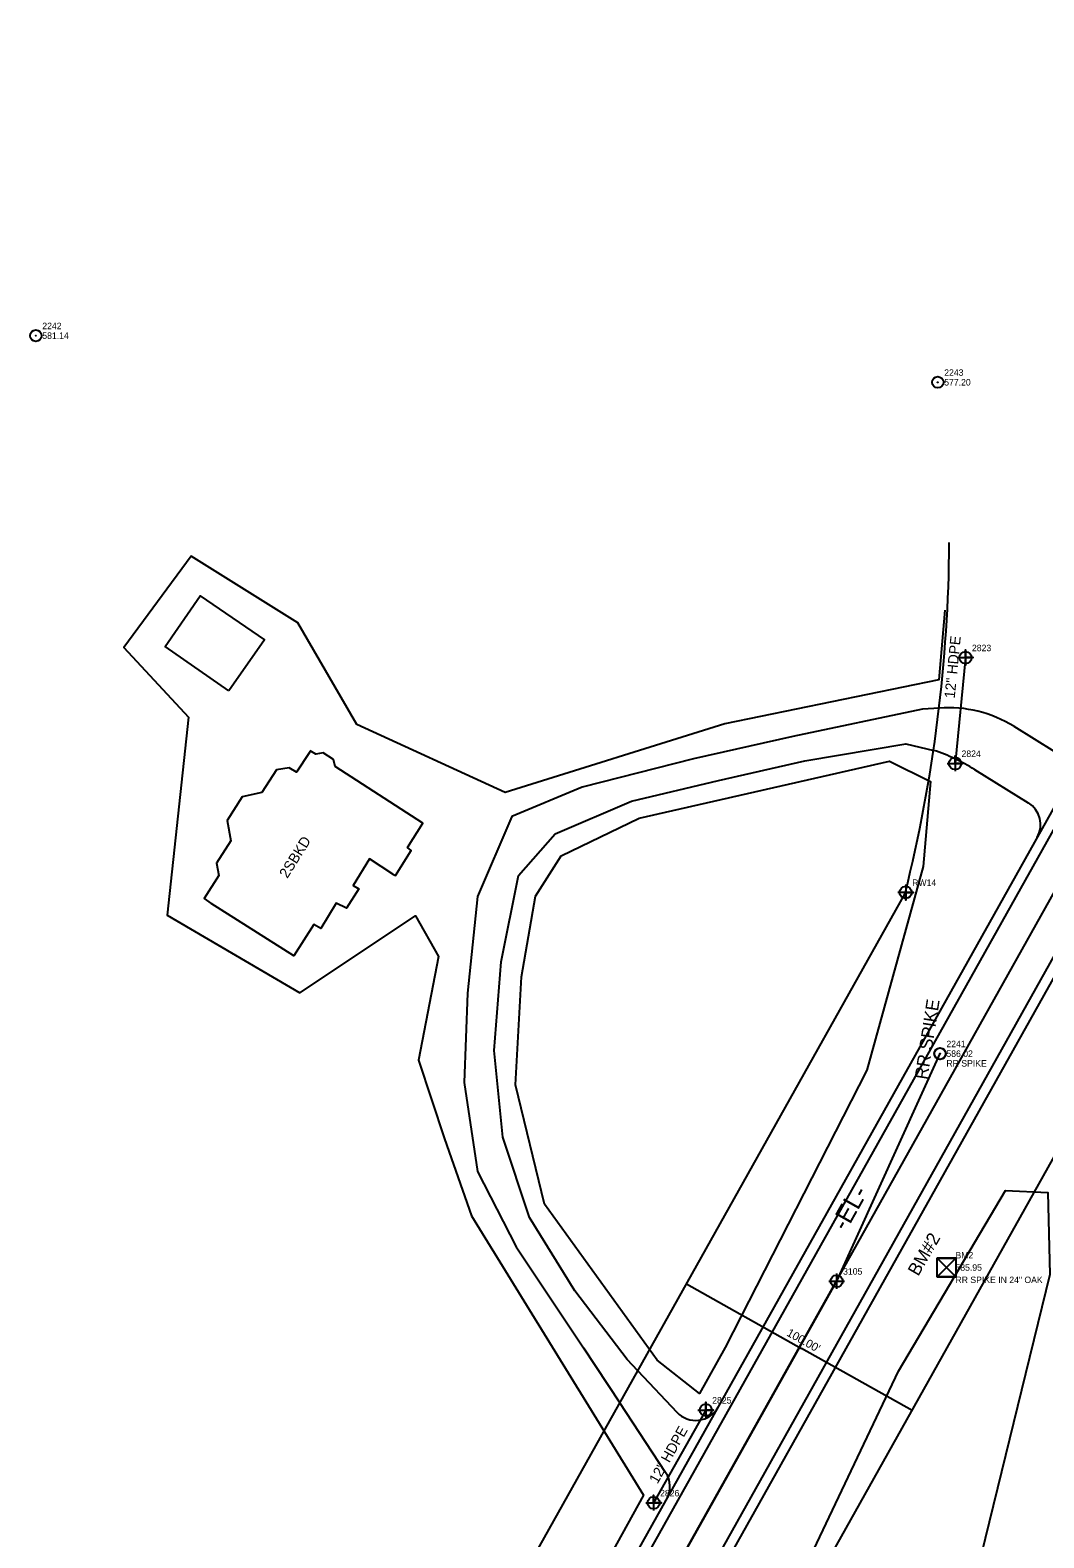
# Model space of a CAD drawing. Extents: x 1653123 to 1656194, y 596584 to 600233.
# Drawn here: x 1654087 to 1654478, y 599047 to 599629 of the extents above; entities that cross this region are included whole.
import ezdxf

# ---------------------------------------------------------------- set-up
doc = ezdxf.new("R2010")
doc.units = 0
for name, color, linetype in [('CTL Bench Mark CELL', 7, 'Continuous'), ('CTL Bench Mark Cogo Comment', 7, 'Continuous'), ('CTL Bench Mark Cogo Elevation', 7, 'Continuous'), ('CTL Bench Mark Cogo Number', 7, 'Continuous'), ('CTL Bench Mark Text', 7, 'Continuous'), ('Default Symbol CELL', 7, 'Continuous'), ('Default Symbol Cogo Number', 7, 'Continuous'), ('Exist Building Foundations', 7, 'Continuous'), ('Exist Building Text', 7, 'Continuous'), ('Exist Horizontal Alignment', 7, 'Continuous'), ('Exist Horizontal Alignment Direction Label', 7, 'Continuous'), ('Exist Property Iron Pin CELL', 7, 'Continuous'), ('Exist Property Iron Pin Cogo Comment', 7, 'Continuous'), ('Exist Property Iron Pin Cogo Elevation', 7, 'Continuous'), ('Exist Property Iron Pin Cogo Number', 7, 'Continuous'), ('Exist Property Iron Pin Text', 7, 'Continuous'), ('Exist Right of Way Line', 7, 'Continuous'), ('Exist Right of Way Width CELL', 7, 'Continuous'), ('Exist Roads EOT', 7, 'Continuous'), ('Exist Structure Minor Pipes HDPE 12 Inch', 7, 'Continuous'), ('Exist Structure Minor Pipes HDPE 12 Inch Cogo Number', 7, 'Continuous'), ('Exist Structure Minor Pipes HDPE 12 Inch Cogo Point CELL', 7, 'Continuous'), ('Exist Structure Minor Pipes HDPE 12 Inch Text', 7, 'Continuous'), ('Exist Vegetation Woods Line', 7, 'Continuous'), ('Prop Conc Shoulder Berm Gutter', 7, 'Continuous'), ('Prop Easement Construction', 7, 'Continuous'), ('Prop Easement Permanent Drainage Station Offsets', 7, 'Continuous'), ('Scratch_Level_5', 7, 'Continuous')]:
    doc.layers.add(name, color=color, linetype=linetype)

# ---------------------------------------------------------------- blocks, each defined once
blk = doc.blocks.new('EXIST STRUCTURE MINOR PIPES HDPE COGO POINT')
at = {"layer": 'Exist Structure Minor Pipes HDPE 12 Inch Cogo Point CELL'}
blk.add_lwpolyline([(-0.06, 0), (0.06, 0), (0, 0), (0, 0.06), (0, -0.06)], dxfattribs=at)
blk.add_circle((0, 0), 0.0469, dxfattribs=at)
blk = doc.blocks.new('EXIST PROPERTY IRON PIN')
at = {"layer": 'Exist Property Iron Pin CELL'}
for radius in [0.0441, 0.00141]:
    blk.add_circle((0.0015, 0), radius, dxfattribs=at)
blk = doc.blocks.new('DEFAULT SYMBOL')
at = {"layer": 'Default Symbol CELL'}
for points in [[(-0.06, 0), (0, 0)], [(0, 0.06), (0, 0)], [(0, 0), (0.06, 0)], [(0, 0), (0, -0.06)]]:
    blk.add_lwpolyline(points, dxfattribs=at)
blk.add_circle((0, 0), 0.0469, dxfattribs=at)

msp = doc.modelspace()

# ---------------------------------------------------------------- linework, layer by layer
at = {"layer": 'CTL Bench Mark CELL'}
msp.add_line((1654440.7, 599151.65), (1654440.7, 599151.65), dxfattribs=at)
msp.add_lwpolyline([(1654437.1, 599155.24), (1654444.29, 599155.24), (1654444.29, 599148.05), (1654437.1, 599148.05)], close=True, dxfattribs=at)
for points in [[(1654444.29, 599155.24), (1654437.1, 599148.05), (1654440.69, 599151.65), (1654444.29, 599148.05), (1654437.1, 599155.24)], [(1654440.69, 599151.65), (1654444.29, 599155.24), (1654437.1, 599155.24), (1654440.69, 599151.65)], [(1654440.69, 599151.65), (1654437.1, 599148.05), (1654444.29, 599148.05), (1654440.69, 599151.65)]]:
    msp.add_lwpolyline(points, dxfattribs=at)
at = {"layer": 'Default Symbol CELL'}
msp.add_lwpolyline([(1654424.97, 599299.49), (1654424.97, 599293.49), (1654424.97, 599296.49), (1654427.97, 599296.49), (1654421.97, 599296.49)], dxfattribs=at)
msp.add_circle((1654424.97, 599296.49), 2.34, dxfattribs=at)
at = {"layer": 'Exist Building Foundations'}
msp.add_lwpolyline([(1654163.44, 599374.25), (1654138.82, 599391.4), (1654152.42, 599411.04), (1654177.25, 599394), (1654163.44, 599374.25)], dxfattribs=at)
at = {"layer": 'Exist Horizontal Alignment'}
msp.add_line((1654156.07, 598714.4), (1654668.85, 599629.4), dxfattribs=at)
at = {"layer": 'Exist Property Iron Pin CELL'}
for centre, radius in [((1654088.9, 599511.44), 2.2), ((1654088.9, 599511.44), 0.0707), ((1654437.36, 599493.44), 2.2), ((1654437.36, 599493.44), 0.0707), ((1654438.2, 599234.23), 2.2), ((1654438.2, 599234.23), 0.0707)]:
    msp.add_circle(centre, radius, dxfattribs=at)
at = {"layer": 'Exist Right of Way Line'}
for points in [[(1654112.46, 598738.84), (1654424.73, 599296.06)], [(1654199.69, 598689.96), (1654529.92, 599279.22)]]:
    msp.add_lwpolyline(points, dxfattribs=at)
msp.add_arc((1653868.71, 599435), 573.11, 345.97002, 359.65316, dxfattribs=at)
at = {"layer": 'Exist Right of Way Width CELL'}
for p in [(1654340.24, 599145.3), (1654427.48, 599096.42)]:
    msp.add_line(p, (1654384.76, 599120.36), dxfattribs=at)
at = {"layer": 'Exist Roads EOT'}
for p, q in [((1654145.61, 598720.27), (1654530.63, 599407.31)), ((1654166.54, 598708.53), (1654551.57, 599395.58))]:
    msp.add_line(p, q, dxfattribs=at)
at = {"layer": 'Exist Structure Minor Pipes HDPE 12 Inch'}
for p, q in [((1654448.08, 599387.12), (1654444.05, 599346.27)), ((1654347.72, 599096.63), (1654327.59, 599060.79))]:
    msp.add_line(p, q, dxfattribs=at)
at = {"layer": 'Exist Vegetation Woods Line'}
for points in [[(1654355.08, 599361.58), (1654270.28, 599335.1), (1654212.97, 599361.37), (1654190.17, 599400.59), (1654148.95, 599426.27), (1654122.87, 599391.08), (1654147.89, 599364.1), (1654139.62, 599287.73), (1654190.89, 599257.69), (1654235.59, 599287.48), (1654244.41, 599271.77), (1654236.79, 599231.73), (1654246.8, 599201.33), (1654257.22, 599171.65), (1654323.7, 599063.8), (1654263.27, 598954.38)], [(1654440.07, 599405.46), (1654437.8, 599378.52), (1654355.08, 599361.58)], [(1654276.56, 599263.87), (1654281.97, 599295.04), (1654291.89, 599310.58), (1654321.99, 599325.1), (1654418.72, 599347.12), (1654434.5, 599339.25), (1654431.74, 599306.54), (1654409.99, 599227.82), (1654355.19, 599120.8), (1654345.35, 599102.98), (1654328.91, 599115.85), (1654285.42, 599176.17), (1654274.28, 599222.2), (1654276.56, 599263.87)], [(1654374.86, 599011.86), (1654422.22, 599111.69), (1654463.55, 599181.33), (1654479.91, 599180.61), (1654480.67, 599148.95), (1654452.57, 599034.46), (1654453.71, 598969.38), (1654444.98, 598946.78), (1654428.73, 598949.23), (1654387.88, 598973.7), (1654377.17, 598996.27), (1654374.86, 599011.86)]]:
    msp.add_lwpolyline(points, dxfattribs=at)
at = {"layer": 'Prop Conc Shoulder Berm Gutter'}
for p, q in [((1654142.12, 598722.22), (1654527.14, 599409.27)), ((1654170.03, 598706.58), (1654555.06, 599393.62))]:
    msp.add_line(p, q, dxfattribs=at)
at = {"layer": 'Prop Easement Construction'}
for p, q in [((1654466.73, 599360.61), (1654482.45, 599350.87)), ((1654451.57, 599343.93), (1654472.35, 599331.06)), ((1654321.47, 599111.81), (1654336.57, 599095.78)), ((1654332.23, 599072.52), (1654314.52, 599099.4))]:
    msp.add_line(p, q, dxfattribs=at)
for points in [[(1654437.98, 599367.65), (1654431.53, 599367.19), (1654381.38, 599356.67), (1654342.94, 599348.11), (1654299.95, 599337.18), (1654272.79, 599325.8), (1654259.59, 599294.89), (1654255.68, 599257.54), (1654254.41, 599223.15), (1654259.52, 599188.75), (1654274.53, 599159.65), (1654300.55, 599120.59), (1654314.52, 599099.4)], [(1654321.47, 599111.81), (1654317.35, 599116.17), (1654297.16, 599142.7), (1654279.61, 599170.99), (1654269.29, 599201.94), (1654266, 599235.5), (1654268.68, 599269.62), (1654275.42, 599303.02), (1654289.54, 599319.05), (1654319.03, 599331.72), (1654352.67, 599339.68), (1654385.99, 599347.25), (1654424.97, 599353.91), (1654435.86, 599351.33)]]:
    msp.add_lwpolyline(points, dxfattribs=at)
for centre, radius, start, end in [((1654441.5, 599319.89), 47.9, 58.22536, 94.22466), ((1654411.53, 599279.29), 76.04, 58.22536, 71.34228), ((1654467.09, 599322.56), 10, 330.73321, 58.22536), ((1654343.85, 599102.64), 10, 223.3068, 330.73321), ((1654323.88, 599067.02), 10, 330.73321, 33.38938)]:
    msp.add_arc(centre, radius, start, end, dxfattribs=at)
at = {"layer": 'Prop Easement Permanent Drainage Station Offsets'}
for points in [[(1654194.9, 599351.11), (1654194.59, 599350.54), (1654189.6, 599342.96), (1654186.84, 599344.58), (1654181.92, 599343.78), (1654176.25, 599335.07), (1654168.58, 599333.35), (1654162.77, 599324.2), (1654164.25, 599316.39), (1654158.76, 599307.71), (1654159.6, 599303.01), (1654153.99, 599294.14), (1654156.61, 599292.22)], [(1654226.77, 599303.56), (1654227.84, 599303.07), (1654233.92, 599312.66), (1654232.44, 599313.76), (1654238.42, 599323.28), (1654204.56, 599345.16), (1654203.95, 599347.75), (1654199.94, 599350.35), (1654197.09, 599349.91), (1654194.9, 599351.11)], [(1654226.77, 599303.56), (1654217.86, 599309.4), (1654211.48, 599299.12), (1654213.64, 599297.83), (1654208.91, 599290.34), (1654204.99, 599292.32), (1654198.99, 599282.54), (1654196.28, 599284.03), (1654188.6, 599272.01), (1654156.61, 599292.22)]]:
    msp.add_lwpolyline(points, dxfattribs=at)
at = {"layer": 'Scratch_Level_5'}
for p, q in [((1654438.2, 599234.23), (1654398.29, 599146.4)), ((1654398.29, 599146.4), (1654321.04, 599008.84))]:
    msp.add_line(p, q, dxfattribs=at)

# ---------------------------------------------------------------- block references
at = {"layer": 'Default Symbol CELL', "xscale": 50, "yscale": 50}
msp.add_blockref('DEFAULT SYMBOL', (1654398.29, 599146.4), dxfattribs=at)
at = {"layer": 'Exist Property Iron Pin CELL', "xscale": 50, "yscale": 50}
msp.add_blockref('EXIST PROPERTY IRON PIN', (1654438.2, 599234.23), dxfattribs=at)
at = {"layer": 'Exist Structure Minor Pipes HDPE 12 Inch Cogo Point CELL', "xscale": 50, "yscale": 50}
for p in [(1654448.08, 599387.12), (1654444.05, 599346.27), (1654347.72, 599096.63), (1654327.59, 599060.79)]:
    msp.add_blockref('EXIST STRUCTURE MINOR PIPES HDPE COGO POINT', p, dxfattribs=at)

# ---------------------------------------------------------------- texts
at = {"layer": 'CTL Bench Mark Cogo Comment'}
msp.add_text('RR SPIKE IN 24" OAK', height=2.5, dxfattribs=at).set_placement((1654444.2, 599145.65))
at = {"layer": 'CTL Bench Mark Cogo Elevation'}
msp.add_text('585.95', height=2.5, dxfattribs=at).set_placement((1654444.2, 599150.4))
at = {"layer": 'CTL Bench Mark Cogo Number'}
msp.add_text('BM2', height=2.5, dxfattribs=at).set_placement((1654444.2, 599155.15))
at = {"layer": 'CTL Bench Mark Text'}
msp.add_text('BM#2', height=5, rotation=59.9255, dxfattribs=at).set_placement((1654429.8, 599148.04))
at = {"layer": 'Default Symbol Cogo Number'}
for s, p in [('RW14', (1654427.47, 599298.99)), ('3105', (1654400.79, 599148.9))]:
    msp.add_text(s, height=2.5, dxfattribs=at).set_placement(p)
at = {"layer": 'Exist Building Text'}
msp.add_text('2SBKD', height=4, rotation=58.01831, dxfattribs=at).set_placement((1654186.07, 599301.67))
at = {"layer": 'Exist Horizontal Alignment Direction Label'}
msp.add_text('-EL-', height=7, rotation=60.73321, dxfattribs=at).set_placement((1654401.92, 599165.36))
at = {"layer": 'Exist Property Iron Pin Cogo Comment'}
msp.add_text('RR SPIKE', height=2.5, dxfattribs=at).set_placement((1654440.7, 599229.23))
at = {"layer": 'Exist Property Iron Pin Cogo Elevation'}
for s, p in [('581.14', (1654091.4, 599510.2)), ('577.20', (1654439.86, 599492.19)), ('586.02', (1654440.7, 599232.98))]:
    msp.add_text(s, height=2.5, dxfattribs=at).set_placement(p)
at = {"layer": 'Exist Property Iron Pin Cogo Number'}
for s, p in [('2242', (1654091.4, 599513.95)), ('2243', (1654439.86, 599495.94)), ('2241', (1654440.7, 599236.73)), ('2241', (1654440.7, 599236.73))]:
    msp.add_text(s, height=2.5, dxfattribs=at).set_placement(p)
at = {"layer": 'Exist Property Iron Pin Text'}
msp.add_text('RR SPIKE', height=5, rotation=81.14591, dxfattribs=at).set_placement((1654433.32, 599224))
at = {"layer": 'Exist Right of Way Width CELL'}
msp.add_text("100.00'", height=3.2, rotation=330.73321, dxfattribs=at).set_placement((1654378.69, 599125.5))
at = {"layer": 'Exist Structure Minor Pipes HDPE 12 Inch Cogo Number'}
for s, p in [('2823', (1654450.58, 599389.62)), ('2824', (1654446.55, 599348.77)), ('2825', (1654350.22, 599099.13)), ('2826', (1654330.09, 599063.29))]:
    msp.add_text(s, height=2.5, dxfattribs=at).set_placement(p)
at = {"layer": 'Exist Structure Minor Pipes HDPE 12 Inch Text'}
for rotation, p in [(84.35455, (1654443.9, 599371.26)), (60.67801, (1654329.08, 599067.86))]:
    msp.add_text('12" HDPE', height=4, rotation=rotation, dxfattribs=at).set_placement(p)

doc.saveas('drawing.dxf')
